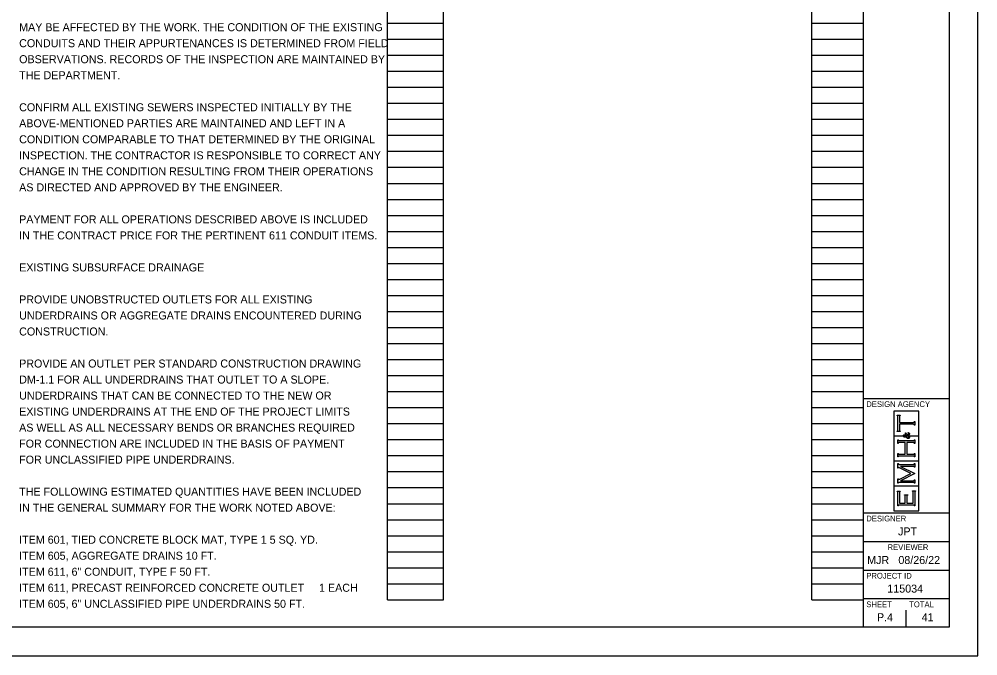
# Model space of a CAD drawing. Extents: x 0 to 34, y -49.5 to 22.
# Drawn here: x 17.24 to 34, y 0 to 11.13 of the extents above; entities that cross this region are included whole.
import ezdxf

# ---------------------------------------------------------------- set-up
doc = ezdxf.new("R2010")
doc.units = 0
for name, color, linetype in [('SH_Border', 7, 'Continuous'), ('SH_Cut_Line', 7, 'Continuous'), ('SH_Data', 7, 'Continuous'), ('SH_Text', 7, 'Continuous')]:
    doc.layers.add(name, color=color, linetype=linetype)

msp = doc.modelspace()

# ---------------------------------------------------------------- linework, layer by layer
at = {"layer": 'SH_Border'}
for p, q in [((32, 0.5), (32, 21.5)), ((32, 4.5), (33.5, 4.5)), ((32, 2.5), (33.5, 2.5)), ((32, 2), (33.5, 2)), ((32, 1.5), (33.5, 1.5)), ((32, 1), (33.5, 1))]:
    msp.add_line(p, q, dxfattribs=at)
msp.add_lwpolyline([(1.5, 21.5), (33.5, 21.5), (33.5, 0.5), (1.5, 0.5)], close=True, dxfattribs=at)
at = {"layer": 'SH_Cut_Line'}
msp.add_lwpolyline([(0, 0), (34, 0), (34, 22), (0, 22)], close=True, dxfattribs=at)
at = {"layer": 'SH_Data'}
for p, q in [((23.68, 0.98), (23.68, 21.14)), ((24.66, 0.98), (24.66, 21.14)), ((31.1, 0.98), (31.1, 21.14)), ((32, 0.98), (32, 21.14)), ((23.68, 11.06), (24.66, 11.06)), ((31.1, 11.06), (32, 11.06)), ((23.68, 10.78), (24.66, 10.78)), ((31.1, 10.78), (32, 10.78)), ((23.68, 10.5), (24.66, 10.5)), ((31.1, 10.5), (32, 10.5)), ((23.68, 10.22), (24.66, 10.22)), ((31.1, 10.22), (32, 10.22)), ((23.68, 9.94), (24.66, 9.94)), ((31.1, 9.94), (32, 9.94)), ((23.68, 9.66), (24.66, 9.66)), ((31.1, 9.66), (32, 9.66)), ((23.68, 9.38), (24.66, 9.38)), ((31.1, 9.38), (32, 9.38)), ((23.68, 9.1), (24.66, 9.1)), ((31.1, 9.1), (32, 9.1)), ((23.68, 8.82), (24.66, 8.82)), ((31.1, 8.82), (32, 8.82)), ((23.68, 8.54), (24.66, 8.54)), ((31.1, 8.54), (32, 8.54)), ((23.68, 8.26), (24.66, 8.26)), ((31.1, 8.26), (32, 8.26)), ((23.68, 7.98), (24.66, 7.98)), ((31.1, 7.98), (32, 7.98)), ((23.68, 7.7), (24.66, 7.7)), ((31.1, 7.7), (32, 7.7)), ((23.68, 7.42), (24.66, 7.42)), ((31.1, 7.42), (32, 7.42)), ((23.68, 7.14), (24.66, 7.14)), ((31.1, 7.14), (32, 7.14)), ((23.68, 6.86), (24.66, 6.86)), ((31.1, 6.86), (32, 6.86)), ((23.68, 6.58), (24.66, 6.58)), ((31.1, 6.58), (32, 6.58)), ((23.68, 6.3), (24.66, 6.3)), ((31.1, 6.3), (32, 6.3)), ((23.68, 6.02), (24.66, 6.02)), ((31.1, 6.02), (32, 6.02)), ((23.68, 5.74), (24.66, 5.74)), ((31.1, 5.74), (32, 5.74)), ((23.68, 5.46), (24.66, 5.46)), ((31.1, 5.46), (32, 5.46)), ((23.68, 5.18), (24.66, 5.18)), ((31.1, 5.18), (32, 5.18)), ((23.68, 4.9), (24.66, 4.9)), ((31.1, 4.9), (32, 4.9)), ((23.68, 4.62), (24.66, 4.62)), ((31.1, 4.62), (32, 4.62)), ((23.68, 4.34), (24.66, 4.34)), ((31.1, 4.34), (32, 4.34)), ((32.966, 4.28), (32.534, 4.28)), ((32.534, 4.28), (32.534, 3.848)), ((32.588, 4.199), (32.588, 4.206)), ((32.588, 4.206), (32.644, 4.206)), ((32.594, 4.198), (32.588, 4.199)), ((32.598, 4.196), (32.594, 4.198)), ((32.599, 4.194), (32.598, 4.196)), ((32.601, 4.191), (32.599, 4.194)), ((32.602, 4.187), (32.601, 4.191)), ((32.632, 4.191), (32.631, 4.187)), ((32.633, 4.194), (32.632, 4.191)), ((32.635, 4.196), (32.633, 4.194)), ((32.639, 4.198), (32.635, 4.196)), ((32.644, 4.199), (32.639, 4.198)), ((32.644, 4.206), (32.644, 4.199)), ((32.966, 3.848), (32.966, 4.28)), ((23.68, 4.06), (24.66, 4.06)), ((31.1, 4.06), (32, 4.06)), ((32.602, 4.181), (32.602, 4.187)), ((32.602, 3.947), (32.602, 4.181)), ((32.631, 4.187), (32.631, 4.181)), ((32.631, 4.181), (32.631, 4.081)), ((32.631, 4.081), (32.872, 4.081)), ((32.872, 4.047), (32.631, 4.047)), ((32.631, 4.047), (32.631, 3.947)), ((32.872, 4.081), (32.878, 4.081)), ((32.878, 4.047), (32.872, 4.047)), ((32.878, 4.081), (32.882, 4.082)), ((32.883, 4.046), (32.878, 4.047)), ((32.882, 4.082), (32.885, 4.084)), ((32.885, 4.044), (32.883, 4.046)), ((32.885, 4.084), (32.887, 4.085)), ((32.888, 4.042), (32.885, 4.044)), ((32.887, 4.085), (32.889, 4.089)), ((32.889, 4.039), (32.888, 4.042)), ((32.889, 4.089), (32.891, 4.095)), ((32.891, 4.033), (32.889, 4.039)), ((32.891, 4.095), (32.898, 4.095)), ((32.898, 4.033), (32.891, 4.033)), ((32.898, 4.095), (32.898, 4.033)), ((32.588, 3.928), (32.594, 3.93)), ((32.588, 3.921), (32.588, 3.928)), ((32.644, 3.921), (32.588, 3.921)), ((32.594, 3.93), (32.598, 3.932)), ((32.598, 3.932), (32.599, 3.934)), ((32.599, 3.934), (32.601, 3.937)), ((32.601, 3.937), (32.602, 3.941)), ((32.602, 3.941), (32.602, 3.947)), ((32.631, 3.947), (32.631, 3.941)), ((32.631, 3.941), (32.632, 3.937)), ((32.632, 3.937), (32.633, 3.934)), ((32.633, 3.934), (32.635, 3.932)), ((32.635, 3.932), (32.639, 3.93)), ((32.639, 3.93), (32.644, 3.928)), ((32.644, 3.928), (32.644, 3.921)), ((32.701, 3.852), (32.703, 3.857)), ((32.703, 3.857), (32.706, 3.861)), ((32.706, 3.861), (32.71, 3.864)), ((32.71, 3.864), (32.714, 3.866)), ((32.712, 3.856), (32.71, 3.854)), ((32.715, 3.857), (32.712, 3.856)), ((32.714, 3.866), (32.719, 3.866)), ((32.718, 3.857), (32.715, 3.857)), ((32.723, 3.857), (32.718, 3.857)), ((32.719, 3.866), (32.724, 3.866)), ((32.727, 3.856), (32.723, 3.857)), ((32.724, 3.866), (32.728, 3.864)), ((32.73, 3.853), (32.727, 3.856)), ((32.728, 3.864), (32.732, 3.861)), ((32.732, 3.861), (32.736, 3.857)), ((32.736, 3.857), (32.74, 3.851)), ((32.738, 3.867), (32.738, 3.898)), ((32.738, 3.898), (32.741, 3.898)), ((32.741, 3.867), (32.738, 3.867)), ((32.741, 3.898), (32.741, 3.894)), ((32.741, 3.894), (32.742, 3.891)), ((32.742, 3.871), (32.741, 3.869)), ((32.741, 3.869), (32.741, 3.867)), ((32.742, 3.891), (32.744, 3.889)), ((32.743, 3.872), (32.742, 3.871)), ((32.745, 3.873), (32.743, 3.872)), ((32.744, 3.889), (32.745, 3.887)), ((32.745, 3.887), (32.75, 3.883)), ((32.747, 3.874), (32.745, 3.873)), ((32.749, 3.874), (32.747, 3.874)), ((32.756, 3.874), (32.749, 3.874)), ((32.75, 3.883), (32.757, 3.879)), ((32.764, 3.87), (32.756, 3.874)), ((32.757, 3.879), (32.765, 3.875)), ((32.775, 3.861), (32.764, 3.87)), ((32.765, 3.875), (32.772, 3.87)), ((32.765, 3.855), (32.775, 3.861)), ((32.772, 3.87), (32.779, 3.865)), ((32.779, 3.865), (32.784, 3.869)), ((32.781, 3.9), (32.783, 3.902)), ((32.785, 3.899), (32.781, 3.9)), ((32.783, 3.902), (32.79, 3.901)), ((32.784, 3.869), (32.787, 3.873)), ((32.788, 3.897), (32.785, 3.899)), ((32.787, 3.873), (32.789, 3.876)), ((32.789, 3.895), (32.788, 3.897)), ((32.791, 3.892), (32.789, 3.895)), ((32.789, 3.876), (32.791, 3.88)), ((32.794, 3.859), (32.789, 3.855)), ((32.79, 3.901), (32.795, 3.898)), ((32.792, 3.89), (32.791, 3.892)), ((32.791, 3.88), (32.792, 3.883)), ((32.792, 3.886), (32.792, 3.89)), ((32.792, 3.883), (32.792, 3.886)), ((32.798, 3.864), (32.794, 3.859)), ((32.795, 3.898), (32.799, 3.894)), ((32.8, 3.868), (32.798, 3.864)), ((32.799, 3.894), (32.802, 3.89)), ((32.802, 3.872), (32.8, 3.868)), ((32.802, 3.89), (32.803, 3.885)), ((32.803, 3.876), (32.802, 3.872)), ((32.803, 3.885), (32.803, 3.88)), ((32.803, 3.88), (32.803, 3.876)), ((23.68, 3.78), (24.66, 3.78)), ((31.1, 3.78), (32, 3.78)), ((32.534, 3.848), (32.693, 3.848)), ((32.693, 3.842), (32.534, 3.842)), ((32.534, 3.842), (32.534, 3.41)), ((32.602, 3.714), (32.602, 3.776)), ((32.602, 3.776), (32.609, 3.776)), ((32.609, 3.714), (32.602, 3.714)), ((32.609, 3.776), (32.611, 3.77)), ((32.61, 3.72), (32.609, 3.714)), ((32.612, 3.723), (32.61, 3.72)), ((32.611, 3.77), (32.612, 3.766)), ((32.612, 3.766), (32.615, 3.765)), ((32.615, 3.725), (32.612, 3.723)), ((32.615, 3.765), (32.617, 3.763)), ((32.617, 3.727), (32.615, 3.725)), ((32.617, 3.763), (32.622, 3.762)), ((32.622, 3.728), (32.617, 3.727)), ((32.622, 3.762), (32.628, 3.762)), ((32.628, 3.728), (32.622, 3.728)), ((32.628, 3.762), (32.872, 3.762)), ((32.732, 3.728), (32.628, 3.728)), ((32.693, 3.848), (32.693, 3.842)), ((32.701, 3.846), (32.701, 3.852)), ((32.701, 3.84), (32.701, 3.846)), ((32.703, 3.835), (32.701, 3.84)), ((32.706, 3.83), (32.703, 3.835)), ((32.707, 3.852), (32.706, 3.849)), ((32.706, 3.849), (32.706, 3.846)), ((32.706, 3.846), (32.706, 3.842)), ((32.706, 3.842), (32.708, 3.839)), ((32.71, 3.824), (32.706, 3.83)), ((32.71, 3.854), (32.707, 3.852)), ((32.708, 3.839), (32.711, 3.837)), ((32.717, 3.821), (32.71, 3.824)), ((32.711, 3.837), (32.714, 3.835)), ((32.714, 3.835), (32.716, 3.834)), ((32.716, 3.834), (32.719, 3.834)), ((32.725, 3.821), (32.717, 3.821)), ((32.719, 3.834), (32.722, 3.834)), ((32.722, 3.834), (32.724, 3.834)), ((32.724, 3.834), (32.727, 3.835)), ((32.728, 3.821), (32.725, 3.821)), ((32.727, 3.835), (32.73, 3.836)), ((32.731, 3.822), (32.728, 3.821)), ((32.734, 3.85), (32.73, 3.853)), ((32.73, 3.836), (32.734, 3.837)), ((32.734, 3.822), (32.731, 3.822)), ((32.732, 3.525), (32.732, 3.728)), ((32.737, 3.845), (32.734, 3.85)), ((32.734, 3.837), (32.74, 3.839)), ((32.737, 3.823), (32.734, 3.822)), ((32.74, 3.839), (32.737, 3.845)), ((32.741, 3.825), (32.737, 3.823)), ((32.74, 3.851), (32.745, 3.842)), ((32.746, 3.827), (32.741, 3.825)), ((32.745, 3.842), (32.755, 3.848)), ((32.753, 3.815), (32.746, 3.827)), ((32.757, 3.832), (32.751, 3.829)), ((32.751, 3.829), (32.755, 3.824)), ((32.759, 3.808), (32.753, 3.815)), ((32.755, 3.848), (32.765, 3.855)), ((32.755, 3.824), (32.758, 3.819)), ((32.762, 3.835), (32.757, 3.832)), ((32.758, 3.819), (32.762, 3.817)), ((32.765, 3.803), (32.759, 3.808)), ((32.872, 3.728), (32.76, 3.728)), ((32.76, 3.728), (32.76, 3.525)), ((32.766, 3.838), (32.762, 3.835)), ((32.762, 3.817), (32.766, 3.814)), ((32.77, 3.799), (32.765, 3.803)), ((32.77, 3.84), (32.766, 3.838)), ((32.766, 3.814), (32.771, 3.812)), ((32.776, 3.845), (32.77, 3.84)), ((32.776, 3.797), (32.77, 3.799)), ((32.771, 3.812), (32.775, 3.812)), ((32.775, 3.812), (32.78, 3.812)), ((32.785, 3.851), (32.776, 3.845)), ((32.782, 3.797), (32.776, 3.797)), ((32.78, 3.812), (32.785, 3.814)), ((32.788, 3.797), (32.782, 3.797)), ((32.789, 3.846), (32.785, 3.851)), ((32.785, 3.814), (32.789, 3.817)), ((32.793, 3.8), (32.788, 3.797)), ((32.789, 3.855), (32.795, 3.849)), ((32.792, 3.842), (32.789, 3.846)), ((32.789, 3.817), (32.793, 3.821)), ((32.793, 3.839), (32.792, 3.842)), ((32.794, 3.837), (32.793, 3.839)), ((32.793, 3.821), (32.795, 3.825)), ((32.797, 3.804), (32.793, 3.8)), ((32.795, 3.834), (32.794, 3.837)), ((32.795, 3.849), (32.798, 3.843)), ((32.795, 3.831), (32.795, 3.834)), ((32.795, 3.825), (32.795, 3.831)), ((32.801, 3.809), (32.797, 3.804)), ((32.798, 3.843), (32.8, 3.839)), ((32.8, 3.839), (32.802, 3.834)), ((32.803, 3.815), (32.801, 3.809)), ((32.802, 3.834), (32.803, 3.829)), ((32.807, 3.842), (32.803, 3.848)), ((32.803, 3.848), (32.966, 3.848)), ((32.803, 3.829), (32.803, 3.823)), ((32.803, 3.823), (32.803, 3.815)), ((32.966, 3.842), (32.807, 3.842)), ((32.872, 3.762), (32.878, 3.762)), ((32.878, 3.728), (32.872, 3.728)), ((32.878, 3.762), (32.882, 3.763)), ((32.883, 3.727), (32.878, 3.728)), ((32.882, 3.763), (32.885, 3.765)), ((32.885, 3.725), (32.883, 3.727)), ((32.885, 3.765), (32.887, 3.766)), ((32.888, 3.723), (32.885, 3.725)), ((32.887, 3.766), (32.889, 3.77)), ((32.889, 3.72), (32.888, 3.723)), ((32.889, 3.77), (32.891, 3.776)), ((32.891, 3.714), (32.889, 3.72)), ((32.891, 3.776), (32.898, 3.776)), ((32.898, 3.714), (32.891, 3.714)), ((32.898, 3.776), (32.898, 3.714)), ((32.966, 3.41), (32.966, 3.842)), ((32.602, 3.477), (32.602, 3.538)), ((32.602, 3.538), (32.609, 3.538)), ((32.609, 3.538), (32.611, 3.533)), ((32.611, 3.533), (32.612, 3.529)), ((32.612, 3.529), (32.615, 3.527)), ((32.615, 3.527), (32.617, 3.526)), ((32.617, 3.526), (32.622, 3.525)), ((32.622, 3.525), (32.628, 3.525)), ((32.628, 3.525), (32.732, 3.525)), ((32.76, 3.525), (32.872, 3.525)), ((32.872, 3.525), (32.878, 3.525)), ((32.878, 3.525), (32.883, 3.525)), ((32.883, 3.525), (32.885, 3.527)), ((32.885, 3.527), (32.888, 3.529)), ((32.888, 3.529), (32.889, 3.533)), ((32.889, 3.533), (32.891, 3.538)), ((32.891, 3.538), (32.898, 3.538)), ((32.898, 3.538), (32.898, 3.477)), ((23.68, 3.5), (24.66, 3.5)), ((31.1, 3.5), (32, 3.5)), ((32.534, 3.41), (32.966, 3.41)), ((32.966, 3.405), (32.534, 3.405)), ((32.534, 3.405), (32.534, 2.973)), ((32.609, 3.477), (32.602, 3.477)), ((32.602, 3.283), (32.602, 3.36)), ((32.602, 3.36), (32.609, 3.36)), ((32.61, 3.482), (32.609, 3.477)), ((32.609, 3.36), (32.611, 3.354)), ((32.612, 3.486), (32.61, 3.482)), ((32.611, 3.354), (32.612, 3.351)), ((32.615, 3.488), (32.612, 3.486)), ((32.617, 3.49), (32.615, 3.488)), ((32.622, 3.491), (32.617, 3.49)), ((32.628, 3.491), (32.622, 3.491)), ((32.872, 3.491), (32.628, 3.491)), ((32.75, 3.5), (32.75, 3.5)), ((32.878, 3.491), (32.872, 3.491)), ((32.883, 3.49), (32.878, 3.491)), ((32.885, 3.488), (32.883, 3.49)), ((32.887, 3.486), (32.885, 3.488)), ((32.887, 3.351), (32.889, 3.354)), ((32.889, 3.482), (32.887, 3.486)), ((32.891, 3.477), (32.889, 3.482)), ((32.889, 3.354), (32.891, 3.36)), ((32.898, 3.477), (32.891, 3.477)), ((32.891, 3.36), (32.898, 3.36)), ((32.898, 3.36), (32.898, 3.298)), ((32.966, 2.973), (32.966, 3.405)), ((23.68, 3.22), (24.66, 3.22)), ((31.1, 3.22), (32, 3.22)), ((32.609, 3.283), (32.602, 3.283)), ((32.612, 3.29), (32.609, 3.283)), ((32.612, 3.351), (32.615, 3.349)), ((32.615, 3.293), (32.612, 3.29)), ((32.615, 3.349), (32.617, 3.347)), ((32.618, 3.293), (32.615, 3.293)), ((32.617, 3.347), (32.622, 3.346)), ((32.621, 3.293), (32.618, 3.293)), ((32.626, 3.292), (32.621, 3.293)), ((32.622, 3.346), (32.628, 3.346)), ((32.633, 3.288), (32.626, 3.292)), ((32.628, 3.346), (32.872, 3.346)), ((32.831, 3.189), (32.633, 3.288)), ((32.635, 3.09), (32.831, 3.189)), ((32.872, 3.312), (32.649, 3.312)), ((32.649, 3.312), (32.898, 3.186)), ((32.898, 3.186), (32.649, 3.062)), ((32.872, 3.346), (32.878, 3.346)), ((32.878, 3.312), (32.872, 3.312)), ((32.878, 3.346), (32.882, 3.347)), ((32.883, 3.311), (32.878, 3.312)), ((32.882, 3.347), (32.885, 3.349)), ((32.885, 3.31), (32.883, 3.311)), ((32.885, 3.349), (32.887, 3.351)), ((32.887, 3.308), (32.885, 3.31)), ((32.889, 3.304), (32.887, 3.308)), ((32.891, 3.298), (32.889, 3.304)), ((32.898, 3.298), (32.891, 3.298)), ((32.602, 3.017), (32.602, 3.094)), ((32.602, 3.094), (32.609, 3.094)), ((32.609, 3.017), (32.602, 3.017)), ((32.609, 3.094), (32.612, 3.087)), ((32.61, 3.023), (32.609, 3.017)), ((32.612, 3.026), (32.61, 3.023)), ((32.612, 3.087), (32.615, 3.083)), ((32.615, 3.028), (32.612, 3.026)), ((32.615, 3.083), (32.618, 3.083)), ((32.617, 3.03), (32.615, 3.028)), ((32.622, 3.031), (32.617, 3.03)), ((32.618, 3.083), (32.62, 3.083)), ((32.62, 3.083), (32.625, 3.086)), ((32.628, 3.031), (32.622, 3.031)), ((32.625, 3.086), (32.635, 3.09)), ((32.872, 3.031), (32.628, 3.031)), ((32.649, 3.062), (32.872, 3.062)), ((32.872, 3.062), (32.878, 3.062)), ((32.878, 3.031), (32.872, 3.031)), ((32.878, 3.062), (32.882, 3.063)), ((32.883, 3.03), (32.878, 3.031)), ((32.882, 3.063), (32.885, 3.065)), ((32.885, 3.028), (32.883, 3.03)), ((32.885, 3.065), (32.887, 3.067)), ((32.887, 3.026), (32.885, 3.028)), ((32.887, 3.067), (32.889, 3.07)), ((32.889, 3.023), (32.887, 3.026)), ((32.889, 3.07), (32.891, 3.076)), ((32.891, 3.017), (32.889, 3.023)), ((32.891, 3.076), (32.898, 3.076)), ((32.898, 3.017), (32.891, 3.017)), ((32.898, 3.076), (32.898, 3.017)), ((23.68, 2.94), (24.66, 2.94)), ((31.1, 2.94), (32, 2.94)), ((32.534, 2.973), (32.966, 2.973)), ((32.966, 2.967), (32.534, 2.967)), ((32.534, 2.967), (32.534, 2.535)), ((32.588, 2.874), (32.588, 2.881)), ((32.588, 2.881), (32.644, 2.881)), ((32.594, 2.873), (32.588, 2.874)), ((32.598, 2.871), (32.594, 2.873)), ((32.599, 2.868), (32.598, 2.871)), ((32.601, 2.866), (32.599, 2.868)), ((32.602, 2.862), (32.601, 2.866)), ((32.602, 2.856), (32.602, 2.862)), ((32.602, 2.621), (32.602, 2.856)), ((32.632, 2.866), (32.631, 2.862)), ((32.631, 2.862), (32.631, 2.856)), ((32.631, 2.856), (32.631, 2.669)), ((32.633, 2.868), (32.632, 2.866)), ((32.635, 2.871), (32.633, 2.868)), ((32.639, 2.873), (32.635, 2.871)), ((32.644, 2.874), (32.639, 2.873)), ((32.644, 2.881), (32.644, 2.874)), ((32.855, 2.877), (32.855, 2.884)), ((32.855, 2.884), (32.912, 2.884)), ((32.861, 2.876), (32.855, 2.877)), ((32.865, 2.874), (32.861, 2.876)), ((32.867, 2.872), (32.865, 2.874)), ((32.868, 2.869), (32.867, 2.872)), ((32.869, 2.865), (32.868, 2.869)), ((32.869, 2.859), (32.869, 2.865)), ((32.869, 2.669), (32.869, 2.859)), ((32.899, 2.869), (32.898, 2.865)), ((32.898, 2.865), (32.898, 2.858)), ((32.898, 2.858), (32.898, 2.621)), ((32.901, 2.871), (32.899, 2.869)), ((32.903, 2.874), (32.901, 2.871)), ((32.906, 2.876), (32.903, 2.874)), ((32.912, 2.877), (32.906, 2.876)), ((32.912, 2.884), (32.912, 2.877)), ((32.966, 2.535), (32.966, 2.967)), ((32.718, 2.81), (32.718, 2.816)), ((32.718, 2.816), (32.774, 2.816)), ((32.723, 2.808), (32.718, 2.81)), ((32.727, 2.806), (32.723, 2.808)), ((32.729, 2.804), (32.727, 2.806)), ((32.731, 2.801), (32.729, 2.804)), ((32.732, 2.797), (32.731, 2.801)), ((32.732, 2.791), (32.732, 2.797)), ((32.732, 2.669), (32.732, 2.791)), ((32.761, 2.801), (32.76, 2.797)), ((32.76, 2.797), (32.76, 2.791)), ((32.76, 2.791), (32.76, 2.669)), ((32.763, 2.804), (32.761, 2.801)), ((32.765, 2.806), (32.763, 2.804)), ((32.768, 2.808), (32.765, 2.806)), ((32.774, 2.81), (32.768, 2.808)), ((32.774, 2.816), (32.774, 2.81)), ((23.68, 2.66), (24.66, 2.66)), ((31.1, 2.66), (32, 2.66)), ((32.534, 2.535), (32.966, 2.535)), ((32.609, 2.621), (32.602, 2.621)), ((32.611, 2.626), (32.609, 2.621)), ((32.612, 2.63), (32.611, 2.626)), ((32.615, 2.632), (32.612, 2.63)), ((32.617, 2.634), (32.615, 2.632)), ((32.622, 2.635), (32.617, 2.634)), ((32.628, 2.635), (32.622, 2.635)), ((32.872, 2.635), (32.628, 2.635)), ((32.631, 2.669), (32.732, 2.669)), ((32.76, 2.669), (32.869, 2.669)), ((32.878, 2.635), (32.872, 2.635)), ((32.883, 2.634), (32.878, 2.635)), ((32.885, 2.632), (32.883, 2.634)), ((32.887, 2.63), (32.885, 2.632)), ((32.889, 2.627), (32.887, 2.63)), ((32.891, 2.621), (32.889, 2.627)), ((32.898, 2.621), (32.891, 2.621)), ((23.68, 2.38), (24.66, 2.38)), ((31.1, 2.38), (32, 2.38)), ((23.68, 2.1), (24.66, 2.1)), ((31.1, 2.1), (32, 2.1)), ((23.68, 1.82), (24.66, 1.82)), ((31.1, 1.82), (32, 1.82)), ((23.68, 1.54), (24.66, 1.54)), ((31.1, 1.54), (32, 1.54)), ((23.68, 1.26), (24.66, 1.26)), ((31.1, 1.26), (32, 1.26)), ((23.68, 0.98), (24.66, 0.98)), ((31.1, 0.98), (32, 0.98)), ((32.375, 0.675), (32.375, 0.675)), ((32.75, 0.5), (32.75, 0.8))]:
    msp.add_line(p, q, dxfattribs=at)

# ---------------------------------------------------------------- texts
for s, height, p in [('DESIGN AGENCY', 0.1, (32.05, 4.35)), ('DESIGNER', 0.1, (32.05, 2.35)), ('JPT', 0.14, (32.605, 2.105)), ('REVIEWER', 0.1, (32.422, 1.85)), ('MJR', 0.14, (32.065, 1.605)), ('08/26/22', 0.14, (32.611, 1.605)), ('PROJECT ID', 0.1, (32.05, 1.35)), ('115034', 0.14, (32.418, 1.105)), ('SHEET', 0.1, (32.05, 0.85)), ('TOTAL', 0.1, (32.8, 0.85)), ('P.4', 0.14, (32.237, 0.605)), ('41', 0.14, (33.019, 0.605))]:
    msp.add_text(s, height=height, dxfattribs=at).set_placement(p)
at = {"layer": 'SH_Text'}
for s, p in [('MAY BE AFFECTED BY THE WORK. THE CONDITION OF THE EXISTING', (17.24, 10.92)), ('CONDUITS AND THEIR APPURTENANCES IS DETERMINED FROM FIELD', (17.24, 10.64)), ('OBSERVATIONS. RECORDS OF THE INSPECTION ARE MAINTAINED BY', (17.24, 10.36)), ('THE DEPARTMENT.', (17.24, 10.08)), ('CONFIRM ALL EXISTING SEWERS INSPECTED INITIALLY BY THE', (17.24, 9.52)), ('ABOVE-MENTIONED PARTIES ARE MAINTAINED AND LEFT IN A', (17.24, 9.24)), ('CONDITION COMPARABLE TO THAT DETERMINED BY THE ORIGINAL', (17.24, 8.96)), ('INSPECTION. THE CONTRACTOR IS RESPONSIBLE TO CORRECT ANY', (17.24, 8.68)), ('CHANGE IN THE CONDITION RESULTING FROM THEIR OPERATIONS', (17.24, 8.4)), ('AS DIRECTED AND APPROVED BY THE ENGINEER.', (17.24, 8.12)), ('PAYMENT FOR ALL OPERATIONS DESCRIBED ABOVE IS INCLUDED', (17.24, 7.56)), ('IN THE CONTRACT PRICE FOR THE PERTINENT 611 CONDUIT ITEMS.', (17.24, 7.28)), ('EXISTING SUBSURFACE DRAINAGE', (17.24, 6.72)), ('PROVIDE UNOBSTRUCTED OUTLETS FOR ALL EXISTING', (17.24, 6.16)), ('UNDERDRAINS OR AGGREGATE DRAINS ENCOUNTERED DURING', (17.24, 5.88)), ('CONSTRUCTION.', (17.24, 5.6)), ('PROVIDE AN OUTLET PER STANDARD CONSTRUCTION DRAWING', (17.24, 5.04)), ('DM-1.1 FOR ALL UNDERDRAINS THAT OUTLET TO A SLOPE.', (17.24, 4.76)), ('UNDERDRAINS THAT CAN BE CONNECTED TO THE NEW OR', (17.24, 4.48)), ('EXISTING UNDERDRAINS AT THE END OF THE PROJECT LIMITS', (17.24, 4.2)), ('AS WELL AS ALL NECESSARY BENDS OR BRANCHES REQUIRED', (17.24, 3.92)), ('FOR CONNECTION ARE INCLUDED IN THE BASIS OF PAYMENT', (17.24, 3.64)), ('FOR UNCLASSIFIED PIPE UNDERDRAINS.', (17.24, 3.36)), ('THE FOLLOWING ESTIMATED QUANTITIES HAVE BEEN INCLUDED', (17.24, 2.8)), ('IN THE GENERAL SUMMARY FOR THE WORK NOTED ABOVE:', (17.24, 2.52)), ('ITEM 601, TIED CONCRETE BLOCK MAT, TYPE 1 5 SQ. YD.', (17.24, 1.96)), ('ITEM 605, AGGREGATE DRAINS 10 FT.', (17.24, 1.68)), ('ITEM 611, 6" CONDUIT, TYPE F 50 FT.', (17.24, 1.4)), ('ITEM 611, PRECAST REINFORCED CONCRETE OUTLET     1 EACH', (17.24, 1.12)), ('ITEM 605, 6" UNCLASSIFIED PIPE UNDERDRAINS 50 FT.', (17.24, 0.84))]:
    msp.add_text(s, height=0.14, dxfattribs=at).set_placement(p)

doc.saveas('drawing.dxf')
